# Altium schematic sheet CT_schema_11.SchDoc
size 146 x 119 mm
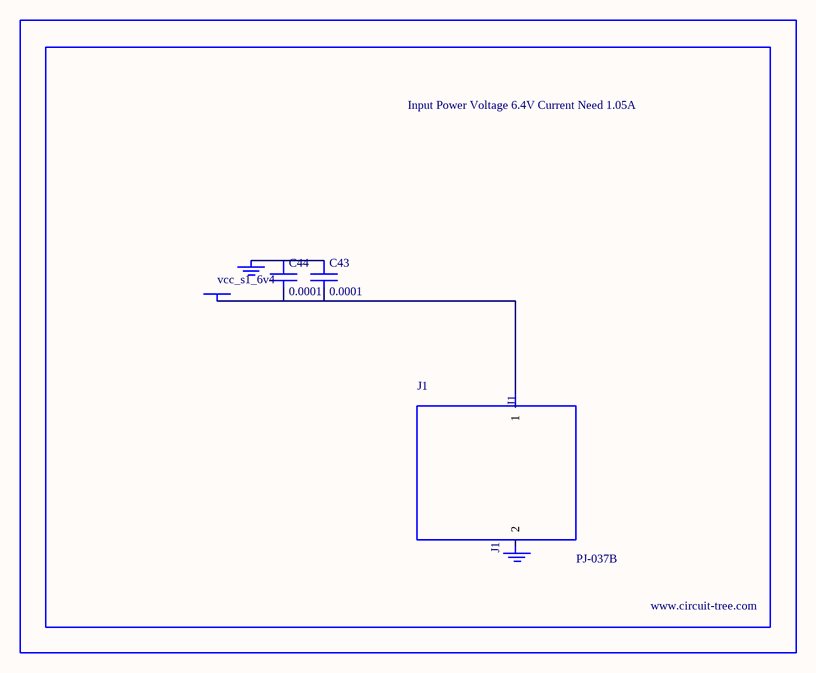
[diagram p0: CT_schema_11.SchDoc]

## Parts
BORDER10  (no value)
C43  0.0001  [EXV-9H]
C44  0.0001  [EXV-9H]
GND_INSTANCE_10_0  (no value)
GND_INSTANCE_10_1  (no value)
J1  PJ-037B  [PJ-037B_PACKAGE]
POWER_INSTANCE_10_0  vcc_s1_6v4

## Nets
NetC43_1: C43.1 C44.1 GND_INSTANCE_10_0.0(GND)
NetC43_2: C43.2 C44.2 J1.1 POWER_INSTANCE_10_0.0(PWR)

Not connected (* = marked no-connect by the designer): GND_INSTANCE_10_1 0(GND); J1 2

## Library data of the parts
BORDER10 = BORDER_PAGE10
C43 C44 = EDK107M035A9HAA
GND_INSTANCE_10_0 GND_INSTANCE_10_1 = GND
POWER_INSTANCE_10_0 = PWR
